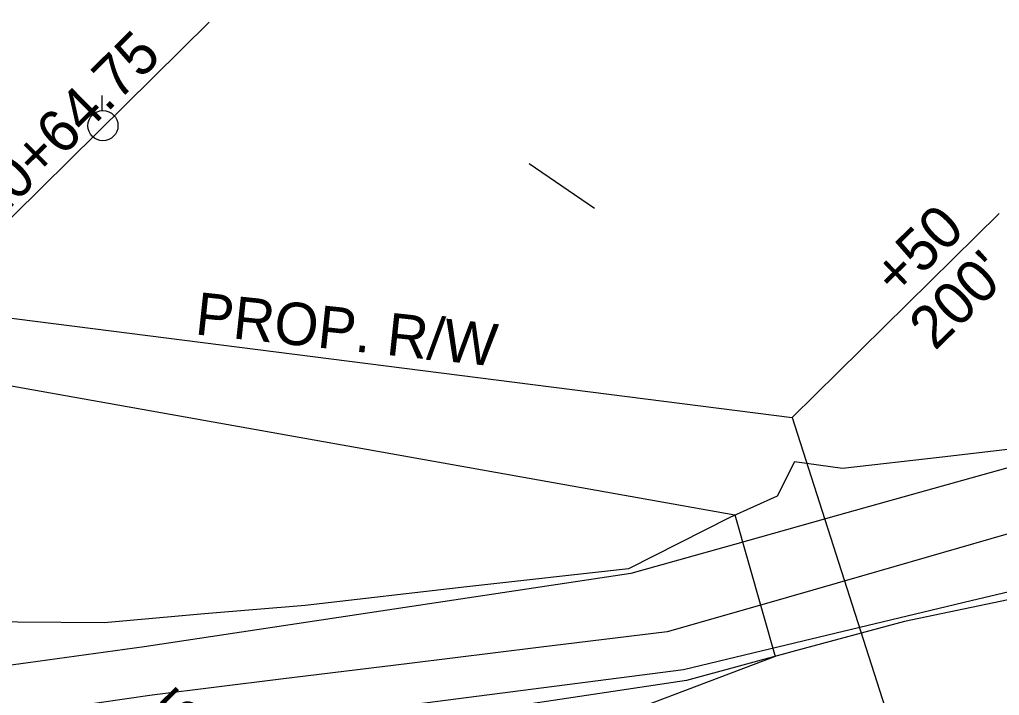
# Model space of a CAD drawing. Extents: x 1660112 to 1662239, y 668919 to 671377.
# Drawn here: x 1661383 to 1661521.6, y 670278 to 670373.6 of the extents above; entities that cross this region are included whole.
import ezdxf

# ---------------------------------------------------------------- set-up
doc = ezdxf.new("R2010")
doc.units = 0
for name, color, linetype in [('R_Annotation', 7, 'Continuous'), ('R_Horz Alg', 7, 'Continuous'), ('R_Horz Alg Annot', 7, 'Continuous'), ('R_Proposed Const Limits_Cut', 7, 'Continuous'), ('R_ROW', 7, 'Continuous'), ('R_ROW Annot', 7, 'Continuous'), ('S_DITCHLINE', 7, 'Continuous'), ('S_STREAM', 7, 'Continuous'), ('S_UTILITY_POLE', 7, 'Continuous')]:
    doc.layers.add(name, color=color, linetype=linetype)

msp = doc.modelspace()

# ---------------------------------------------------------------- linework, layer by layer
at = {"layer": 'R_Horz Alg'}
msp.add_arc((1655846.99, 664877.91), 7639.44, 42.561815, 45.430038, dxfattribs=at)
at = {"layer": 'R_Horz Alg Annot'}
msp.add_lwpolyline([(1661322.68, 670287.26), (1661409.79, 670373.24)], dxfattribs=at)
at = {"layer": 'R_Proposed Const Limits_Cut'}
msp.add_lwpolyline([(1661343.39, 670328.65), (1661484.18, 670303.54), (1661489.92, 670283.53), (1661399.85, 670249.44)], dxfattribs=at)
at = {"layer": 'R_ROW'}
for points in [[(1661180, 670399.59), (1661317.24, 670367), (1661356.6, 670334.6), (1661492.29, 670317.34)], [(1661492.29, 670317.34), (1661506.22, 670273.91), (1661412.98, 670233.91), (1661445.83, 670132.9)]]:
    msp.add_lwpolyline(points, dxfattribs=at)
at = {"layer": 'R_ROW Annot'}
msp.add_line((1661492.29, 670317.34), (1661521.59, 670346.19), dxfattribs=at)
at = {"layer": 'S_DITCHLINE'}
msp.add_lwpolyline([(1661455.1, 670353.25), (1661464.33, 670346.92)], dxfattribs=at)
at = {"layer": 'S_STREAM'}
for points in [[(1661620.34, 670335.21), (1661597.17, 670329.75), (1661574, 670324.29), (1661550.82, 670318.83), (1661527.65, 670313.37), (1661513.53, 670311.73), (1661499.41, 670310.09), (1661492.64, 670311.04), (1661490.16, 670306.19), (1661483.49, 670303.19), (1661469.16, 670295.94), (1661446.28, 670293.35), (1661423.4, 670290.75), (1661409.17, 670289.53), (1661394.93, 670288.3), (1661370.48, 670288.49), (1661352.9, 670285.18), (1661335.31, 670281.88), (1661320.32, 670280.07), (1661305.33, 670278.26)], [(1661528.23, 670311.73), (1661513.54, 670307.61), (1661498.85, 670303.49), (1661484.15, 670299.37), (1661469.46, 670295.26), (1661452.24, 670292.66), (1661435.03, 670290.06), (1661417.81, 670287.47), (1661400.59, 670284.87), (1661384.22, 670282.64), (1661367.85, 670280.4)], [(1661623.56, 670311.06), (1661600.76, 670306.67), (1661577.96, 670302.29), (1661555.16, 670297.9), (1661532.36, 670293.52), (1661508.21, 670288.49), (1661492.78, 670284.3), (1661477.36, 670280.12), (1661459.42, 670277.44), (1661441.48, 670274.76), (1661423.55, 670272.09), (1661405.61, 670269.41), (1661388.57, 670266.5), (1661371.54, 670263.59), (1661354.51, 670260.67), (1661337.47, 670257.76), (1661319.37, 670253.79), (1661298.79, 670248.53)], [(1661529.58, 670302.78), (1661515.84, 670298.83), (1661502.1, 670294.89), (1661488.35, 670290.94), (1661474.61, 670287), (1661456.4, 670284.77), (1661438.18, 670282.53), (1661419.96, 670280.3), (1661401.75, 670278.07), (1661386.08, 670275.8), (1661370.4, 670273.52)], [(1661531.19, 670294.62), (1661517.62, 670291.37), (1661504.05, 670288.12), (1661490.48, 670284.87), (1661476.91, 670281.62), (1661458.63, 670279.27), (1661440.34, 670276.92), (1661422.06, 670274.57), (1661403.77, 670272.22), (1661387.42, 670269.33), (1661371.06, 670266.44)]]:
    msp.add_lwpolyline(points, dxfattribs=at)
at = {"layer": 'S_UTILITY_POLE'}
msp.add_line((1661394.66, 670360.74), (1661394.66, 670362.85), dxfattribs=at)
msp.add_circle((1661394.78, 670358.6), 2.13, dxfattribs=at)

# ---------------------------------------------------------------- texts
at = {"layer": 'R_Annotation'}
msp.add_text('PROP. R/W', height=6, rotation=353.8746, dxfattribs=at).set_placement((1661407.68, 670329.1))
at = {"layer": 'R_Horz Alg Annot'}
msp.add_text('PI  20+64.75', height=6, rotation=44.6261, dxfattribs=at).set_placement((1661370.73, 670336.09))
at = {"layer": 'R_ROW Annot'}
for s, p in [('+50', (1661507.24, 670334.11)), ("200'", (1661512.5, 670326.67)), ('+55', (1661400, 670265.88))]:
    msp.add_text(s, height=6, rotation=44.328, dxfattribs=at).set_placement(p)

doc.saveas('drawing.dxf')
